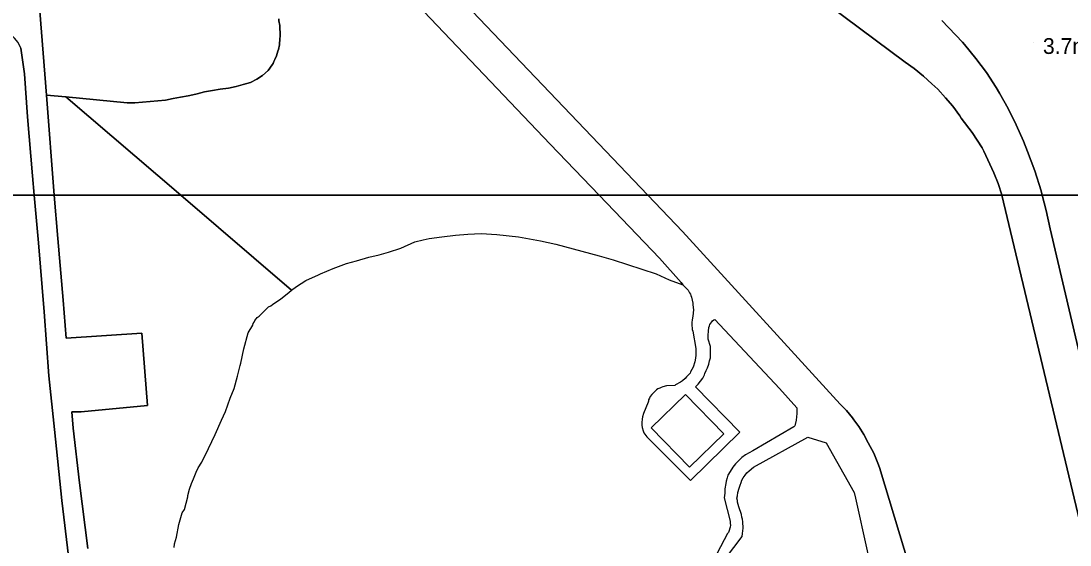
# Model space of a CAD drawing. Extents: x 529240 to 530363, y 179600 to 180767.
# Drawn here: x 529802.4 to 529918.6, y 180075.3 to 180133.3 of the extents above; entities that cross this region are included whole.
import ezdxf

# ---------------------------------------------------------------- set-up
doc = ezdxf.new("R2010")
doc.units = 0
for name, color, linetype in [('General surface', 7, 'Continuous'), ('Natural environment', 7, 'Continuous'), ('Path', 7, 'Continuous'), ('Road Or Track', 7, 'Continuous'), ('Roadside', 7, 'Continuous'), ('Unclassified', 7, 'Continuous')]:
    doc.layers.add(name, color=color, linetype=linetype)

msp = doc.modelspace()

# ---------------------------------------------------------------- linework, layer by layer
at = {"layer": 'General surface'}
for points in [[(529807.4, 180124.9), (529814.2, 180124.25), (529815.05, 180124.25), (529815.9, 180124.3), (529816.75, 180124.4), (529817.6, 180124.45), (529818.45, 180124.55), (529819.3, 180124.7), (529820.1, 180124.85), (529820.95, 180125), (529821.8, 180125.2), (529821.95, 180125.25), (529822.75, 180125.45), (529823.65, 180125.6), (529824.5, 180125.75), (529825.4, 180125.85), (529826.25, 180126.05), (529827.05, 180126.25), (529827.85, 180126.5), (529828.55, 180126.85), (529829.2, 180127.25), (529829.8, 180127.8), (529830.25, 180128.45), (529830.35, 180128.6), (529830.45, 180128.8), (529830.55, 180129.05), (529830.75, 180129.45), (529830.8, 180129.7), (529830.9, 180129.95), (529830.95, 180130.15), (529831.05, 180130.65), (529831.05, 180130.9), (529831.1, 180131.1), (529831.1, 180131.35), (529831.15, 180131.6), (529831.15, 180132.1), (529831.1, 180132.35), (529831.1, 180132.8), (529831, 180133.3), (529831, 180133.55)], [(529805.25, 180125.1), (529807.4, 180124.9)], [(529807.4, 180124.9), (529820.13, 180114)], [(529819.4, 180075), (529819.45, 180075.4), (529819.65, 180076.15), (529819.9, 180077.55), (529820.3, 180078.85), (529820.55, 180079.2), (529820.9, 180080.6), (529820.9, 180080.75), (529821.1, 180081.45), (529821.3, 180082.1), (529821.55, 180082.6), (529821.85, 180083.35), (529822.05, 180083.8), (529822.45, 180084.45), (529823.2, 180085.95), (529823.95, 180087.5), (529824.65, 180089.1), (529825.1, 180090.05), (529825.6, 180091.55), (529826.05, 180092.6), (529826.4, 180093.95), (529826.7, 180095.15), (529826.8, 180095.4), (529827.1, 180097), (529827.6, 180098.75), (529828.1, 180099.6), (529828.15, 180099.8), (529828.25, 180099.95), (529828.35, 180100.15), (529828.5, 180100.3), (529828.6, 180100.45), (529828.8, 180100.6), (529829.85, 180101.65), (529830.1, 180101.75), (529830.3, 180101.9), (529831.2, 180102.55), (529832.1, 180103.25), (529832.4, 180103.5), (529820.13, 180114), (529806.12, 180114), (529806.5, 180109.2), (529807.1, 180102.4), (529807.43, 180098.19), (529815.81, 180098.74), (529816.44, 180090.71), (529809.11, 180090.03), (529808.06, 180090.01), (529808.2, 180088.2), (529808.9, 180082.15), (529809.85, 180074.9)], [(529820.13, 180114), (529832.4, 180103.5)]]:
    msp.add_lwpolyline(points, dxfattribs=at)
msp.add_lwpolyline([(529806.12, 180114), (529820.13, 180114), (529807.4, 180124.9), (529805.25, 180125.1)], close=True, dxfattribs=at)
at = {"layer": 'Natural environment'}
for points in [[(529822.85, 180165.35), (529871.88, 180114), (529911.11, 180114), (529911.1, 180114.05), (529910.7, 180115.3), (529910.2, 180116.5), (529909.1, 180118.9), (529908.9, 180119.25), (529907.8, 180120.95), (529906.6, 180122.55), (529906.45, 180122.8), (529905.65, 180123.85), (529904.85, 180124.8), (529904, 180125.75), (529903.35, 180126.35), (529902.4, 180127.2), (529901.4, 180128.05), (529900.4, 180128.75), (529836.35, 180176.45)], [(529831, 180133.55), (529831, 180133.3), (529831.1, 180132.8), (529831.1, 180132.35), (529831.15, 180132.1), (529831.15, 180131.6), (529831.1, 180131.35), (529831.1, 180131.1), (529831.05, 180130.9), (529831.05, 180130.65), (529830.95, 180130.15), (529830.9, 180129.95), (529830.8, 180129.7), (529830.75, 180129.45), (529830.55, 180129.05), (529830.45, 180128.8), (529830.35, 180128.6), (529830.25, 180128.45), (529829.8, 180127.8), (529829.2, 180127.25), (529828.55, 180126.85), (529827.85, 180126.5), (529827.05, 180126.25), (529826.25, 180126.05), (529825.4, 180125.85), (529824.5, 180125.75), (529823.65, 180125.6), (529822.75, 180125.45), (529821.95, 180125.25), (529821.8, 180125.2), (529820.95, 180125), (529820.1, 180124.85), (529819.3, 180124.7), (529818.45, 180124.55), (529817.6, 180124.45), (529816.75, 180124.4), (529815.9, 180124.3), (529815.05, 180124.25), (529814.2, 180124.25), (529807.4, 180124.9), (529820.13, 180114), (529866.48, 180114), (529861.05, 180119.65), (529819.85, 180162.95)], [(529804.5, 180134.4), (529805.25, 180125.1), (529807.4, 180124.9), (529814.2, 180124.25), (529815.05, 180124.25), (529815.9, 180124.3), (529816.75, 180124.4), (529817.6, 180124.45), (529818.45, 180124.55), (529819.3, 180124.7), (529820.1, 180124.85), (529820.95, 180125), (529821.8, 180125.2), (529821.95, 180125.25), (529822.75, 180125.45), (529823.65, 180125.6), (529824.5, 180125.75), (529825.4, 180125.85), (529826.25, 180126.05), (529827.05, 180126.25), (529827.85, 180126.5), (529828.55, 180126.85), (529829.2, 180127.25), (529829.8, 180127.8), (529830.25, 180128.45), (529830.35, 180128.6), (529830.45, 180128.8), (529830.55, 180129.05), (529830.75, 180129.45), (529830.8, 180129.7), (529830.9, 180129.95), (529830.95, 180130.15), (529831.05, 180130.65), (529831.05, 180130.9), (529831.1, 180131.1), (529831.1, 180131.35), (529831.15, 180131.6), (529831.15, 180132.1), (529831.1, 180132.35), (529831.1, 180132.8), (529831, 180133.3), (529831, 180133.55)], [(529807.7, 180074.05), (529806.95, 180080.2), (529806.15, 180088.05), (529805.5, 180094), (529805, 180101.1), (529804.35, 180108.75), (529803.89, 180114), (529777.5, 180114)], [(529920.3, 180075.5), (529911.11, 180114), (529871.88, 180114), (529875.7, 180110), (529893.2, 180090.85), (529893.9, 180090.15), (529894.55, 180089.35), (529894.7, 180089.15), (529895.25, 180088.4), (529895.8, 180087.5), (529896.3, 180086.6), (529896.9, 180085.45), (529897.35, 180084.35), (529897.55, 180083.85), (529900.85, 180072.85)]]:
    msp.add_lwpolyline(points, dxfattribs=at)
for points in [[(529777.5, 180114), (529803.89, 180114), (529803.7, 180116.15), (529803.15, 180122.7), (529802.8, 180127.45), (529802.4, 180130.3), (529802.1, 180130.9), (529801.7, 180131.4), (529801.45, 180131.65), (529800.95, 180132.05), (529800.65, 180132.25), (529799.75, 180132.55), (529799.25, 180132.65), (529798.95, 180132.65), (529798.45, 180132.55), (529798.15, 180132.5), (529797.7, 180132.35), (529797.4, 180132.3), (529797.1, 180132.15), (529796.9, 180132), (529795.8, 180131.1), (529778.65, 180115.1)], [(529820.13, 180114), (529832.4, 180103.5), (529832.95, 180103.9), (529834, 180104.55), (529835.4, 180105.2), (529835.6, 180105.3), (529837, 180105.9), (529838.5, 180106.45), (529839.6, 180106.75), (529840.95, 180107.15), (529842.1, 180107.4), (529843.15, 180107.7), (529844.5, 180108.15), (529846.05, 180108.85), (529847, 180109.05), (529847.65, 180109.2), (529849.05, 180109.4), (529850.55, 180109.6), (529851.95, 180109.7), (529853.4, 180109.75), (529855.15, 180109.65), (529857.55, 180109.4), (529860, 180108.95), (529861.7, 180108.6), (529866.5, 180107.3), (529868.05, 180106.85), (529872.8, 180105.3), (529874.25, 180104.65), (529875.75, 180104.1), (529875.55, 180104.35), (529873.15, 180107.05), (529866.48, 180114)]]:
    msp.add_lwpolyline(points, close=True, dxfattribs=at)
at = {"layer": 'Path'}
for points in [[(529871.88, 180114), (529822.85, 180165.35), (529819.85, 180162.95), (529861.05, 180119.65), (529866.48, 180114)], [(529876.05, 180091.95), (529872.25, 180088.25), (529876.5, 180083.9), (529880.3, 180087.6)]]:
    msp.add_lwpolyline(points, close=True, dxfattribs=at)
for points in [[(529802.4, 180130.3), (529802.8, 180127.45), (529803.15, 180122.7), (529803.7, 180116.15), (529803.89, 180114), (529806.12, 180114), (529805.25, 180125.1), (529804.5, 180134.4)], [(529809.85, 180074.9), (529808.9, 180082.15), (529808.2, 180088.2), (529808.06, 180090.01), (529809.11, 180090.03), (529816.44, 180090.71), (529815.81, 180098.74), (529807.43, 180098.19), (529807.1, 180102.4), (529806.5, 180109.2), (529806.12, 180114), (529803.89, 180114), (529804.35, 180108.75), (529805, 180101.1), (529805.5, 180094), (529806.15, 180088.05), (529806.95, 180080.2), (529807.7, 180074.05)], [(529900.85, 180072.85), (529897.55, 180083.85), (529897.35, 180084.35), (529896.9, 180085.45), (529896.3, 180086.6), (529895.8, 180087.5), (529895.25, 180088.4), (529894.7, 180089.15), (529894.55, 180089.35), (529893.9, 180090.15), (529893.2, 180090.85), (529875.7, 180110), (529871.88, 180114), (529866.48, 180114), (529873.15, 180107.05), (529875.55, 180104.35), (529875.75, 180104.1), (529876.35, 180103.5), (529876.5, 180103.2), (529876.6, 180103.05), (529876.65, 180102.9), (529876.7, 180102.7), (529876.8, 180102.4), (529876.85, 180102.05), (529876.85, 180101.85), (529876.95, 180101.3), (529876.85, 180100.6), (529876.8, 180100.2), (529876.75, 180099.9), (529876.75, 180099.5), (529876.8, 180099.35), (529876.8, 180099.15), (529876.85, 180098.95), (529877.2, 180097.05), (529877.2, 180096.3), (529877.15, 180095.95), (529877.1, 180095.55), (529876.9, 180094.95), (529876.6, 180094.45), (529876.55, 180094.3), (529876.15, 180093.9), (529876, 180093.7), (529875.7, 180093.45), (529875.5, 180093.3), (529874.95, 180093), (529874.85, 180092.95), (529873.95, 180092.9), (529873.55, 180092.8), (529873.35, 180092.7), (529873.2, 180092.65), (529873, 180092.55), (529872.85, 180092.45), (529872.55, 180092.15), (529872.3, 180091.95), (529872.15, 180091.7), (529872.05, 180091.55), (529871.95, 180091.35), (529871.95, 180091.2), (529871.9, 180091.1), (529871.4, 180089.85), (529871.3, 180089.45), (529871.25, 180089.2), (529871.2, 180088.85), (529871.2, 180088.55), (529871.25, 180088.3), (529871.35, 180087.9), (529871.45, 180087.7), (529871.75, 180087.25), (529876.6, 180082.4), (529882.05, 180087.75), (529877.15, 180092.8), (529877.45, 180093.1), (529877.7, 180093.4), (529877.95, 180093.75), (529878.15, 180094.1), (529878.2, 180094.25), (529878.35, 180094.6), (529878.5, 180094.9), (529878.65, 180095.3), (529878.7, 180095.65), (529878.8, 180096), (529878.8, 180097.25), (529878.55, 180098.05), (529878.55, 180098.5), (529878.6, 180098.95), (529878.65, 180099.35), (529878.7, 180099.55), (529878.75, 180099.7), (529878.95, 180100), (529879.05, 180100.1), (529879.2, 180100.2), (529879.3, 180100.25), (529886.45, 180092.6), (529888.4, 180090.45), (529888.4, 180089.85), (529888.35, 180089.45), (529888.3, 180089.1), (529888.2, 180088.6), (529888.15, 180088.45), (529888.05, 180088.35), (529883.5, 180085.7), (529882.7, 180085.25), (529882.3, 180084.95), (529881.6, 180084.25), (529881.3, 180083.9), (529880.8, 180083.1), (529880.75, 180083), (529880.65, 180082.7), (529880.55, 180082.35), (529880.5, 180082.1), (529880.4, 180081.5), (529880.4, 180081), (529880.35, 180080.5), (529881, 180077.9), (529881, 180077.65), (529881.05, 180077.45), (529881, 180077.25), (529880.85, 180076.75), (529880.8, 180076.65), (529880.7, 180076.55), (529879.55, 180074.35)], [(529879.45, 180072.4), (529882.33, 180076.23), (529882.35, 180076.55), (529882.45, 180077.15), (529882.4, 180077.85), (529882.35, 180078.15), (529882.3, 180078.35), (529882.25, 180078.65), (529881.95, 180079.5), (529881.9, 180079.75), (529881.8, 180080), (529881.8, 180080.2), (529881.75, 180080.45), (529881.8, 180080.7), (529881.85, 180081.1), (529882, 180081.55), (529882.1, 180081.9), (529882.2, 180082.2), (529882.3, 180082.45), (529882.45, 180082.7), (529882.65, 180083), (529882.85, 180083.25), (529883.1, 180083.5), (529883.6, 180083.9), (529889.6, 180087.2), (529891.65, 180086.6), (529894.75, 180081.1), (529894.9, 180080.45), (529897.45, 180068.8)]]:
    msp.add_lwpolyline(points, dxfattribs=at)
at = {"layer": 'Road Or Track'}
for points in [[(529904.45, 180133.35), (529906.75, 180130.95), (529906.95, 180130.7), (529908.2, 180129.15), (529909.4, 180127.6), (529910.45, 180125.95), (529910.85, 180125.3), (529911.8, 180123.6), (529912.7, 180121.8), (529913.5, 180120), (529913.95, 180118.85), (529914.75, 180116.7), (529915.45, 180114.5), (529915.58, 180114), (529927.95, 180114)], [(529904.45, 180133.35), (529906.75, 180130.95), (529906.95, 180130.7), (529908.2, 180129.15), (529909.4, 180127.6), (529910.45, 180125.95), (529910.85, 180125.3), (529911.8, 180123.6), (529912.7, 180121.8), (529913.5, 180120), (529913.95, 180118.85), (529914.75, 180116.7), (529915.45, 180114.5), (529915.58, 180114)], [(529927.95, 180114), (529915.58, 180114), (529916, 180112.3), (529916.45, 180110.3), (529942.35, 180000)], [(529915.58, 180114), (529916, 180112.3), (529916.45, 180110.3), (529942.35, 180000), (529942.8, 179997.8), (529943.4, 179995.6), (529943.8, 179993.3), (529944.3, 179991.1), (529945.6, 179983.55), (529946.05, 179979.25), (529946.4, 179974.9), (529946.4, 179966.9), (529946.15, 179962.9), (529945.7, 179958.4), (529945, 179954), (529944.05, 179949.4), (529942.95, 179944.8), (529941.4, 179939.4), (529939.75, 179934.9), (529938.3, 179931.7)]]:
    msp.add_lwpolyline(points, dxfattribs=at)
at = {"layer": 'Roadside'}
for points in [[(529836.35, 180176.45), (529900.4, 180128.75), (529901.4, 180128.05), (529902.4, 180127.2), (529903.35, 180126.35), (529904, 180125.75), (529904.85, 180124.8), (529905.65, 180123.85), (529906.45, 180122.8), (529906.6, 180122.55), (529907.8, 180120.95), (529908.9, 180119.25), (529909.1, 180118.9), (529910.2, 180116.5), (529910.7, 180115.3), (529911.1, 180114.05), (529911.11, 180114), (529915.58, 180114), (529915.45, 180114.5), (529914.75, 180116.7), (529913.95, 180118.85), (529913.5, 180120), (529912.7, 180121.8), (529911.8, 180123.6), (529910.85, 180125.3), (529910.45, 180125.95), (529909.4, 180127.6), (529908.2, 180129.15), (529906.95, 180130.7), (529906.75, 180130.95), (529904.45, 180133.35)], [(529942.35, 180000), (529916.45, 180110.3), (529916, 180112.3), (529915.58, 180114), (529911.11, 180114), (529920.3, 180075.5)]]:
    msp.add_lwpolyline(points, dxfattribs=at)
at = {"layer": 'Unclassified'}
msp.add_line((529914.6, 180130.9), (529914.6, 180130.9), dxfattribs=at)
for points in [[(529836.35, 180176.45), (529900.4, 180128.75), (529901.4, 180128.05), (529902.4, 180127.2), (529903.35, 180126.35), (529904, 180125.75), (529904.85, 180124.8), (529905.65, 180123.85), (529906.45, 180122.8), (529906.6, 180122.55), (529907.8, 180120.95), (529908.9, 180119.25), (529909.1, 180118.9), (529910.2, 180116.5), (529910.7, 180115.3), (529911.1, 180114.05), (529911.11, 180114)], [(529822.85, 180165.35), (529871.88, 180114)], [(529819.85, 180162.95), (529861.05, 180119.65), (529866.48, 180114)], [(529803.75, 180151.1), (529805, 180149.15), (529805.2, 180148.85), (529805.5, 180148.05), (529805.75, 180147.05), (529805.8, 180146.65), (529805.8, 180145.35), (529805.75, 180144.7), (529805.65, 180144), (529805.55, 180143.45), (529804.75, 180140.45), (529804.55, 180139.75), (529804.45, 180138.85), (529804.35, 180136.1), (529804.35, 180135.3), (529804.5, 180134.4), (529805.25, 180125.1)], [(529803.89, 180114), (529803.7, 180116.15), (529803.15, 180122.7), (529802.8, 180127.45), (529802.4, 180130.3), (529802.1, 180130.9), (529801.7, 180131.4), (529801.45, 180131.65), (529800.95, 180132.05), (529800.65, 180132.25), (529799.75, 180132.55), (529799.25, 180132.65), (529798.95, 180132.65), (529798.45, 180132.55), (529798.15, 180132.5), (529797.7, 180132.35), (529797.4, 180132.3), (529797.1, 180132.15), (529796.9, 180132), (529795.8, 180131.1), (529778.65, 180115.1), (529777.5, 180114)], [(529805.25, 180125.1), (529806.12, 180114)], [(529792.2, 180006.35), (529808.35, 180016.8), (529808.75, 180017.15), (529809.1, 180017.5), (529809.3, 180017.8), (529809.35, 180017.95), (529809.4, 180018.15), (529809.4, 180018.3), (529813.2, 180036.95), (529813.25, 180037.2), (529813.25, 180037.9), (529813.2, 180038.15), (529813.15, 180038.35), (529813.1, 180038.45), (529811.4, 180050.15), (529810, 180058.95), (529808.85, 180066.6), (529807.7, 180074.05), (529806.95, 180080.2), (529806.15, 180088.05), (529805.5, 180094), (529805, 180101.1), (529804.35, 180108.75), (529803.89, 180114)], [(529806.12, 180114), (529806.5, 180109.2), (529807.1, 180102.4), (529807.43, 180098.19)], [(529866.48, 180114), (529873.15, 180107.05), (529875.55, 180104.35), (529875.75, 180104.1)], [(529871.88, 180114), (529875.7, 180110)], [(529911.11, 180114), (529920.3, 180075.5)]]:
    msp.add_lwpolyline(points, dxfattribs=at)

# ---------------------------------------------------------------- texts
msp.add_text('3.7m', height=1.75, dxfattribs=at).set_placement((529915.65, 180129.65))

doc.saveas('drawing.dxf')
